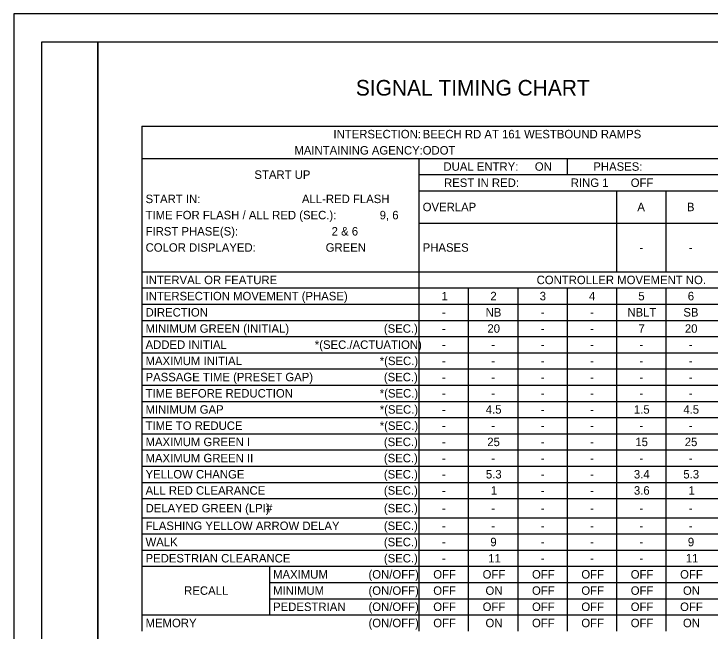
# Model space of a CAD drawing. Extents: x 0 to 34, y 0 to 22.
# Drawn here: x 0 to 12.45, y 10.95 to 22 of the extents above; entities that cross this region are included whole.
import ezdxf

# ---------------------------------------------------------------- set-up
doc = ezdxf.new("R2010")
doc.units = 0
for name, color, linetype in [('SG_P_Text', 7, 'Continuous'), ('SH_Border', 7, 'Continuous'), ('SH_Cut_Line', 7, 'Continuous'), ('SH_Text', 7, 'Continuous')]:
    doc.layers.add(name, color=color, linetype=linetype)

msp = doc.modelspace()

# ---------------------------------------------------------------- linework, layer by layer
at = {"layer": 'SH_Border'}
for points in [[(0.5, 21.5), (1.5, 21.5), (1.5, 0.5), (0.5, 0.5)], [(1.5, 21.5), (33.5, 21.5), (33.5, 0.5), (1.5, 0.5)]]:
    msp.add_lwpolyline(points, close=True, dxfattribs=at)
at = {"layer": 'SH_Cut_Line'}
msp.add_lwpolyline([(0, 0), (34, 0), (34, 22), (0, 22)], close=True, dxfattribs=at)
at = {"layer": 'SH_Text'}
for p, q in [((2.288, 19.994), (7.243, 19.994)), ((2.288, 19.994), (2.288, 19.704)), ((7.243, 19.994), (11.657, 19.994)), ((11.657, 19.994), (14.305, 19.994)), ((2.288, 19.704), (2.288, 19.414)), ((2.288, 19.414), (7.243, 19.414)), ((2.288, 19.414), (2.288, 19.124)), ((7.243, 19.414), (11.657, 19.414)), ((7.243, 19.414), (7.243, 19.124)), ((9.891, 19.414), (9.891, 19.124)), ((11.657, 19.414), (14.305, 19.414)), ((2.288, 19.124), (2.288, 18.834)), ((7.243, 19.124), (11.657, 19.124)), ((7.243, 19.124), (7.243, 18.834)), ((11.657, 19.124), (14.305, 19.124)), ((2.288, 18.834), (2.288, 18.544)), ((7.243, 18.834), (11.657, 18.834)), ((7.243, 18.834), (7.243, 18.544)), ((10.774, 18.834), (10.774, 18.544)), ((11.657, 18.834), (14.305, 18.834)), ((11.657, 18.834), (11.657, 18.544)), ((2.288, 18.544), (2.288, 18.254)), ((7.243, 18.544), (7.243, 18.254)), ((10.774, 18.544), (10.774, 18.254)), ((11.657, 18.544), (11.657, 18.254)), ((2.288, 18.254), (2.288, 17.965)), ((7.243, 18.254), (11.657, 18.254)), ((7.243, 18.254), (7.243, 17.965)), ((10.774, 18.254), (10.774, 17.965)), ((11.657, 18.254), (14.305, 18.254)), ((11.657, 18.254), (11.657, 17.965)), ((2.288, 17.965), (2.288, 17.675)), ((7.243, 17.965), (7.243, 17.675)), ((10.774, 17.965), (10.774, 17.675)), ((11.657, 17.965), (11.657, 17.675)), ((2.288, 17.675), (2.288, 17.385)), ((7.243, 17.675), (7.243, 17.385)), ((10.774, 17.675), (10.774, 17.385)), ((11.657, 17.675), (11.657, 17.385)), ((2.288, 17.385), (7.243, 17.385)), ((2.288, 17.385), (2.288, 17.095)), ((7.243, 17.385), (11.657, 17.385)), ((7.243, 17.385), (7.243, 17.095)), ((11.657, 17.385), (14.305, 17.385)), ((2.288, 17.095), (7.243, 17.095)), ((2.288, 17.095), (2.288, 16.805)), ((7.243, 17.095), (11.657, 17.095)), ((7.243, 17.095), (7.243, 16.805)), ((8.125, 17.095), (8.125, 16.805)), ((9.008, 17.095), (9.008, 16.805)), ((9.891, 17.095), (9.891, 16.805)), ((10.774, 17.095), (10.774, 16.805)), ((11.657, 17.095), (14.305, 17.095)), ((11.657, 17.095), (11.657, 16.805)), ((2.288, 16.805), (7.243, 16.805)), ((2.288, 16.805), (2.288, 16.515)), ((7.243, 16.805), (11.657, 16.805)), ((7.243, 16.805), (7.243, 16.515)), ((8.125, 16.805), (8.125, 16.515)), ((9.008, 16.805), (9.008, 16.515)), ((9.891, 16.805), (9.891, 16.515)), ((10.774, 16.805), (10.774, 16.515)), ((11.657, 16.805), (14.305, 16.805)), ((11.657, 16.805), (11.657, 16.515)), ((2.288, 16.515), (7.243, 16.515)), ((2.288, 16.515), (2.288, 16.225)), ((7.243, 16.515), (11.657, 16.515)), ((7.243, 16.515), (7.243, 16.225)), ((8.125, 16.515), (8.125, 16.225)), ((9.008, 16.515), (9.008, 16.225)), ((9.891, 16.515), (9.891, 16.225)), ((10.774, 16.515), (10.774, 16.225)), ((11.657, 16.515), (14.305, 16.515)), ((11.657, 16.515), (11.657, 16.225)), ((2.288, 16.225), (7.243, 16.225)), ((2.288, 16.225), (2.288, 15.935)), ((7.243, 16.225), (11.657, 16.225)), ((7.243, 16.225), (7.243, 15.935)), ((8.125, 16.225), (8.125, 15.935)), ((9.008, 16.225), (9.008, 15.935)), ((9.891, 16.225), (9.891, 15.935)), ((10.774, 16.225), (10.774, 15.935)), ((11.657, 16.225), (14.305, 16.225)), ((11.657, 16.225), (11.657, 15.935)), ((2.288, 15.935), (7.243, 15.935)), ((2.288, 15.935), (2.288, 15.646)), ((7.243, 15.935), (11.657, 15.935)), ((7.243, 15.935), (7.243, 15.646)), ((8.125, 15.935), (8.125, 15.646)), ((9.008, 15.935), (9.008, 15.646)), ((9.891, 15.935), (9.891, 15.646)), ((10.774, 15.935), (10.774, 15.646)), ((11.657, 15.935), (14.305, 15.935)), ((11.657, 15.935), (11.657, 15.646)), ((2.288, 15.646), (7.243, 15.646)), ((2.288, 15.646), (2.288, 15.356)), ((7.243, 15.646), (11.657, 15.646)), ((7.243, 15.646), (7.243, 15.356)), ((8.125, 15.646), (8.125, 15.356)), ((9.008, 15.646), (9.008, 15.356)), ((9.891, 15.646), (9.891, 15.356)), ((10.774, 15.646), (10.774, 15.356)), ((11.657, 15.646), (14.305, 15.646)), ((11.657, 15.646), (11.657, 15.356)), ((2.288, 15.356), (7.243, 15.356)), ((2.288, 15.356), (2.288, 15.066)), ((7.243, 15.356), (11.657, 15.356)), ((7.243, 15.356), (7.243, 15.066)), ((8.125, 15.356), (8.125, 15.066)), ((9.008, 15.356), (9.008, 15.066)), ((9.891, 15.356), (9.891, 15.066)), ((10.774, 15.356), (10.774, 15.066)), ((11.657, 15.356), (14.305, 15.356)), ((11.657, 15.356), (11.657, 15.066)), ((2.288, 15.066), (7.243, 15.066)), ((2.288, 15.066), (2.288, 14.776)), ((7.243, 15.066), (11.657, 15.066)), ((7.243, 15.066), (7.243, 14.776)), ((8.125, 15.066), (8.125, 14.776)), ((9.008, 15.066), (9.008, 14.776)), ((9.891, 15.066), (9.891, 14.776)), ((10.774, 15.066), (10.774, 14.776)), ((11.657, 15.066), (14.305, 15.066)), ((11.657, 15.066), (11.657, 14.776)), ((2.288, 14.776), (7.243, 14.776)), ((2.288, 14.776), (2.288, 14.486)), ((7.243, 14.776), (11.657, 14.776)), ((7.243, 14.776), (7.243, 14.486)), ((8.125, 14.776), (8.125, 14.486)), ((9.008, 14.776), (9.008, 14.486)), ((9.891, 14.776), (9.891, 14.486)), ((10.774, 14.776), (10.774, 14.486)), ((11.657, 14.776), (14.305, 14.776)), ((11.657, 14.776), (11.657, 14.486)), ((2.288, 14.486), (7.243, 14.486)), ((2.288, 14.486), (2.288, 14.196)), ((7.243, 14.486), (11.657, 14.486)), ((7.243, 14.486), (7.243, 14.196)), ((8.125, 14.486), (8.125, 14.196)), ((9.008, 14.486), (9.008, 14.196)), ((9.891, 14.486), (9.891, 14.196)), ((10.774, 14.486), (10.774, 14.196)), ((11.657, 14.486), (14.305, 14.486)), ((11.657, 14.486), (11.657, 14.196)), ((2.288, 14.196), (7.243, 14.196)), ((2.288, 14.196), (2.288, 13.906)), ((7.243, 14.196), (11.657, 14.196)), ((7.243, 14.196), (7.243, 13.906)), ((8.125, 14.196), (8.125, 13.906)), ((9.008, 14.196), (9.008, 13.906)), ((9.891, 14.196), (9.891, 13.906)), ((10.774, 14.196), (10.774, 13.906)), ((11.657, 14.196), (14.305, 14.196)), ((11.657, 14.196), (11.657, 13.906)), ((2.288, 13.906), (7.243, 13.906)), ((2.288, 13.906), (2.288, 13.616)), ((7.243, 13.906), (11.657, 13.906)), ((7.243, 13.906), (7.243, 13.616)), ((8.125, 13.906), (8.125, 13.616)), ((9.008, 13.906), (9.008, 13.616)), ((9.891, 13.906), (9.891, 13.616)), ((10.774, 13.906), (10.774, 13.616)), ((11.657, 13.906), (14.305, 13.906)), ((11.657, 13.906), (11.657, 13.616)), ((2.288, 13.616), (7.243, 13.616)), ((2.288, 13.616), (2.288, 13.326)), ((7.243, 13.616), (11.657, 13.616)), ((7.243, 13.616), (7.243, 13.326)), ((8.125, 13.616), (8.125, 13.326)), ((9.008, 13.616), (9.008, 13.326)), ((9.891, 13.616), (9.891, 13.326)), ((10.774, 13.616), (10.774, 13.326)), ((11.657, 13.616), (14.305, 13.616)), ((11.657, 13.616), (11.657, 13.326)), ((2.288, 13.326), (7.243, 13.326)), ((2.288, 13.326), (2.288, 12.984)), ((7.243, 13.326), (11.657, 13.326)), ((7.243, 13.326), (7.243, 12.984)), ((8.125, 13.326), (8.125, 12.984)), ((9.008, 13.326), (9.008, 12.984)), ((9.891, 13.326), (9.891, 12.984)), ((10.774, 13.326), (10.774, 12.984)), ((11.657, 13.326), (14.305, 13.326)), ((11.657, 13.326), (11.657, 12.984)), ((2.288, 12.984), (7.243, 12.984)), ((2.288, 12.984), (2.288, 12.694)), ((7.243, 12.984), (11.657, 12.984)), ((7.243, 12.984), (7.243, 12.694)), ((8.125, 12.984), (8.125, 12.694)), ((9.008, 12.984), (9.008, 12.694)), ((9.891, 12.984), (9.891, 12.694)), ((10.774, 12.984), (10.774, 12.694)), ((11.657, 12.984), (14.305, 12.984)), ((11.657, 12.984), (11.657, 12.694)), ((2.288, 12.694), (7.243, 12.694)), ((2.288, 12.694), (2.288, 12.404)), ((7.243, 12.694), (11.657, 12.694)), ((7.243, 12.694), (7.243, 12.404)), ((8.125, 12.694), (8.125, 12.404)), ((9.008, 12.694), (9.008, 12.404)), ((9.891, 12.694), (9.891, 12.404)), ((10.774, 12.694), (10.774, 12.404)), ((11.657, 12.694), (14.305, 12.694)), ((11.657, 12.694), (11.657, 12.404)), ((2.288, 12.404), (7.243, 12.404)), ((2.288, 12.404), (2.288, 12.114)), ((7.243, 12.404), (11.657, 12.404)), ((7.243, 12.404), (7.243, 12.114)), ((8.125, 12.404), (8.125, 12.114)), ((9.008, 12.404), (9.008, 12.114)), ((9.891, 12.404), (9.891, 12.114)), ((10.774, 12.404), (10.774, 12.114)), ((11.657, 12.404), (14.305, 12.404)), ((11.657, 12.404), (11.657, 12.114)), ((2.288, 12.114), (7.243, 12.114)), ((2.288, 12.114), (2.288, 11.824)), ((4.568, 12.114), (4.568, 11.824)), ((7.243, 12.114), (11.657, 12.114)), ((7.243, 12.114), (7.243, 11.824)), ((8.125, 12.114), (8.125, 11.824)), ((9.008, 12.114), (9.008, 11.824)), ((9.891, 12.114), (9.891, 11.824)), ((10.774, 12.114), (10.774, 11.824)), ((11.657, 12.114), (14.305, 12.114)), ((11.657, 12.114), (11.657, 11.824)), ((2.288, 11.824), (2.288, 11.245)), ((4.568, 11.824), (7.243, 11.824)), ((4.568, 11.824), (4.568, 11.245)), ((7.243, 11.824), (11.657, 11.824)), ((7.243, 11.824), (7.243, 11.245)), ((8.125, 11.824), (8.125, 11.245)), ((9.008, 11.824), (9.008, 11.245)), ((9.891, 11.824), (9.891, 11.245)), ((10.774, 11.824), (10.774, 11.245)), ((11.657, 11.824), (14.305, 11.824)), ((11.657, 11.824), (11.657, 11.245)), ((4.568, 11.534), (7.243, 11.534)), ((7.243, 11.534), (11.657, 11.534)), ((11.657, 11.534), (14.305, 11.534)), ((2.288, 11.245), (7.243, 11.245)), ((2.288, 11.245), (2.288, 10.955)), ((7.243, 11.245), (11.657, 11.245)), ((7.243, 11.245), (7.243, 10.955)), ((8.125, 11.245), (8.125, 10.955)), ((9.008, 11.245), (9.008, 10.955)), ((9.891, 11.245), (9.891, 10.955)), ((10.774, 11.245), (10.774, 10.955)), ((11.657, 11.245), (14.305, 11.245)), ((11.657, 11.245), (11.657, 10.955))]:
    msp.add_line(p, q, dxfattribs=at)

# ---------------------------------------------------------------- texts
at = {"layer": 'SG_P_Text'}
msp.add_text('SIGNAL TIMING CHART', height=0.28, dxfattribs=at).set_placement((6.114, 20.538))
at = {"layer": 'SH_Text'}
for s, height, p in [('INTERSECTION:', 0.15153, (5.713, 19.773)), ('BEECH RD AT 161 WESTBOUND RAMPS', 0.15153, (7.309, 19.773)), ('MAINTAINING AGENCY:', 0.15153, (5.015, 19.483)), ('ODOT', 0.1515, (7.309, 19.483)), ('DUAL ENTRY:', 0.15153, (7.68, 19.193)), ('ON', 0.1515, (9.314, 19.193)), ('PHASES:', 0.1515, (10.36, 19.193)), ('START UP', 0.1515, (4.3, 19.048)), ('REST IN RED:', 0.15153, (7.691, 18.903)), ('RING 1', 0.1515, (9.957, 18.903)), ('OFF', 0.1515, (11.029, 18.903)), ('START IN:', 0.1515, (2.354, 18.614)), ('ALL-RED FLASH', 0.15153, (5.15, 18.614)), ('OVERLAP', 0.1515, (7.309, 18.469)), ('A', 0.152, (11.147, 18.469)), ('B', 0.152, (12.034, 18.469)), ('TIME FOR FLASH / ALL RED (SEC.):', 0.15153, (2.354, 18.324)), ('9, 6', 0.1515, (6.54, 18.324)), ('FIRST PHASE(S):', 0.15153, (2.354, 18.034)), ('2 & 6', 0.1515, (5.681, 18.034)), ('COLOR DISPLAYED:', 0.15153, (2.354, 17.744)), ('GREEN', 0.1515, (5.574, 17.744)), ('PHASES', 0.1515, (7.309, 17.744)), ('-', 0.152, (11.184, 17.744)), ('-', 0.152, (12.067, 17.744)), ('INTERVAL OR FEATURE', 0.15153, (2.354, 17.164)), ('CONTROLLER MOVEMENT NO.', 0.15153, (9.346, 17.164)), ('INTERSECTION MOVEMENT (PHASE)', 0.15153, (2.354, 16.874)), ('1', 0.152, (7.647, 16.874)), ('2', 0.152, (8.519, 16.874)), ('3', 0.152, (9.401, 16.874)), ('4', 0.152, (10.282, 16.874)), ('5', 0.152, (11.165, 16.874)), ('6', 0.152, (12.049, 16.874)), ('DIRECTION', 0.1515, (2.354, 16.584)), ('NB', 0.1515, (8.434, 16.584)), ('NBLT', 0.1515, (10.97, 16.584)), ('SB', 0.1515, (11.97, 16.584)), ('-', 0.152, (7.653, 16.584)), ('-', 0.152, (9.419, 16.584)), ('-', 0.152, (10.301, 16.584)), ('MINIMUM GREEN (INITIAL)', 0.15153, (2.354, 16.294)), ('(SEC.)', 0.1515, (6.615, 16.294)), ('20', 0.1515, (8.466, 16.294)), ('7', 0.152, (11.167, 16.294)), ('20', 0.1515, (11.997, 16.294)), ('-', 0.152, (7.653, 16.294)), ('-', 0.152, (9.419, 16.294)), ('-', 0.152, (10.301, 16.294)), ('ADDED INITIAL', 0.15153, (2.354, 16.005)), ('*(SEC./ACTUATION)', 0.15153, (5.38, 16.005)), ('-', 0.152, (7.653, 16.005)), ('-', 0.152, (8.536, 16.005)), ('-', 0.152, (9.419, 16.005)), ('-', 0.152, (10.301, 16.005)), ('-', 0.152, (11.184, 16.005)), ('-', 0.152, (12.067, 16.005)), ('MAXIMUM INITIAL', 0.15153, (2.354, 15.715)), ('*(SEC.)', 0.1515, (6.541, 15.715)), ('-', 0.152, (7.653, 15.715)), ('-', 0.152, (8.536, 15.715)), ('-', 0.152, (9.419, 15.715)), ('-', 0.152, (10.301, 15.715)), ('-', 0.152, (11.184, 15.715)), ('-', 0.152, (12.067, 15.715)), ('PASSAGE TIME (PRESET GAP)', 0.15153, (2.354, 15.425)), ('(SEC.)', 0.1515, (6.615, 15.425)), ('-', 0.152, (7.653, 15.425)), ('-', 0.152, (8.536, 15.425)), ('-', 0.152, (9.419, 15.425)), ('-', 0.152, (10.301, 15.425)), ('-', 0.152, (11.184, 15.425)), ('-', 0.152, (12.067, 15.425)), ('TIME BEFORE REDUCTION', 0.15153, (2.354, 15.135)), ('*(SEC.)', 0.1515, (6.541, 15.135)), ('-', 0.152, (7.653, 15.135)), ('-', 0.152, (8.536, 15.135)), ('-', 0.152, (9.419, 15.135)), ('-', 0.152, (10.301, 15.135)), ('-', 0.152, (11.184, 15.135)), ('-', 0.152, (12.067, 15.135)), ('MINIMUM GAP', 0.15153, (2.354, 14.845)), ('*(SEC.)', 0.1515, (6.541, 14.845)), ('4.5', 0.1515, (8.437, 14.845)), ('1.5', 0.1515, (11.086, 14.845)), ('4.5', 0.1515, (11.969, 14.845)), ('-', 0.152, (7.653, 14.845)), ('-', 0.152, (9.419, 14.845)), ('-', 0.152, (10.301, 14.845)), ('TIME TO REDUCE', 0.15153, (2.354, 14.555)), ('*(SEC.)', 0.1515, (6.541, 14.555)), ('-', 0.152, (7.653, 14.555)), ('-', 0.152, (8.536, 14.555)), ('-', 0.152, (9.419, 14.555)), ('-', 0.152, (10.301, 14.555)), ('-', 0.152, (11.184, 14.555)), ('-', 0.152, (12.067, 14.555)), ('MAXIMUM GREEN I', 0.15153, (2.354, 14.265)), ('(SEC.)', 0.1515, (6.615, 14.265)), ('-', 0.152, (7.653, 14.265)), ('25', 0.1515, (8.464, 14.265)), ('-', 0.152, (9.419, 14.265)), ('-', 0.152, (10.301, 14.265)), ('15', 0.1515, (11.112, 14.265)), ('25', 0.1515, (11.995, 14.265)), ('MAXIMUM GREEN II', 0.15153, (2.354, 13.975)), ('(SEC.)', 0.1515, (6.615, 13.975)), ('-', 0.152, (7.653, 13.975)), ('-', 0.152, (8.536, 13.975)), ('-', 0.152, (9.419, 13.975)), ('-', 0.152, (10.301, 13.975)), ('-', 0.152, (11.184, 13.975)), ('-', 0.152, (12.067, 13.975)), ('YELLOW CHANGE', 0.15153, (2.354, 13.686)), ('(SEC.)', 0.1515, (6.615, 13.686)), ('5.3', 0.1515, (8.439, 13.686)), ('3.4', 0.1515, (11.085, 13.686)), ('5.3', 0.1515, (11.97, 13.686)), ('-', 0.152, (7.653, 13.686)), ('-', 0.152, (9.419, 13.686)), ('-', 0.152, (10.301, 13.686)), ('ALL RED CLEARANCE', 0.15153, (2.354, 13.396)), ('(SEC.)', 0.1515, (6.615, 13.396)), ('-', 0.152, (7.653, 13.396)), ('1', 0.152, (8.529, 13.396)), ('-', 0.152, (9.419, 13.396)), ('-', 0.152, (10.301, 13.396)), ('3.6', 0.1515, (11.086, 13.396)), ('1', 0.152, (12.061, 13.396)), ('DELAYED GREEN (LPI) ', 0.15153, (2.354, 13.079)), ('#', 0.152, (4.507, 13.079)), ('(SEC.)', 0.1515, (6.615, 13.079)), ('-', 0.152, (7.653, 13.079)), ('-', 0.152, (8.536, 13.079)), ('-', 0.152, (9.419, 13.079)), ('-', 0.152, (10.301, 13.079)), ('-', 0.152, (11.184, 13.079)), ('-', 0.152, (12.067, 13.079)), ('FLASHING YELLOW ARROW DELAY', 0.15153, (2.354, 12.763)), ('(SEC.)', 0.1515, (6.615, 12.763)), ('-', 0.152, (7.653, 12.763)), ('-', 0.152, (8.536, 12.763)), ('-', 0.152, (9.419, 12.763)), ('-', 0.152, (10.301, 12.763)), ('-', 0.152, (11.184, 12.763)), ('-', 0.152, (12.067, 12.763)), ('WALK', 0.1515, (2.354, 12.473)), ('(SEC.)', 0.1515, (6.615, 12.473)), ('9', 0.152, (8.518, 12.473)), ('9', 0.152, (12.05, 12.473)), ('-', 0.152, (7.653, 12.473)), ('-', 0.152, (9.419, 12.473)), ('-', 0.152, (10.301, 12.473)), ('-', 0.152, (11.184, 12.473)), ('PEDESTRIAN CLEARANCE', 0.15153, (2.354, 12.183)), ('(SEC.)', 0.1515, (6.615, 12.183)), ('11', 0.1515, (8.482, 12.183)), ('11', 0.1515, (12.013, 12.183)), ('-', 0.152, (7.653, 12.183)), ('-', 0.152, (9.419, 12.183)), ('-', 0.152, (10.301, 12.183)), ('-', 0.152, (11.184, 12.183)), ('MAXIMUM', 0.1515, (4.634, 11.894)), ('(ON/OFF)', 0.1515, (6.34, 11.894)), ('OFF', 0.1515, (7.498, 11.894)), ('OFF', 0.1515, (8.381, 11.894)), ('OFF', 0.1515, (9.264, 11.894)), ('OFF', 0.1515, (10.146, 11.894)), ('OFF', 0.1515, (11.029, 11.894)), ('OFF', 0.1515, (11.912, 11.894)), ('RECALL', 0.1515, (3.044, 11.604)), ('MINIMUM', 0.1515, (4.634, 11.604)), ('(ON/OFF)', 0.1515, (6.34, 11.604)), ('OFF', 0.1515, (7.498, 11.604)), ('ON', 0.1515, (8.432, 11.604)), ('OFF', 0.1515, (9.264, 11.604)), ('OFF', 0.1515, (10.146, 11.604)), ('OFF', 0.1515, (11.029, 11.604)), ('ON', 0.1515, (11.963, 11.604)), ('PEDESTRIAN', 0.1515, (4.634, 11.314)), ('(ON/OFF)', 0.1515, (6.34, 11.314)), ('OFF', 0.1515, (7.498, 11.314)), ('OFF', 0.1515, (8.381, 11.314)), ('OFF', 0.1515, (9.264, 11.314)), ('OFF', 0.1515, (10.146, 11.314)), ('OFF', 0.1515, (11.029, 11.314)), ('OFF', 0.1515, (11.912, 11.314)), ('MEMORY', 0.1515, (2.354, 11.024)), ('(ON/OFF)', 0.1515, (6.34, 11.024)), ('OFF', 0.1515, (7.498, 11.024)), ('ON', 0.1515, (8.432, 11.024)), ('OFF', 0.1515, (9.264, 11.024)), ('OFF', 0.1515, (10.146, 11.024)), ('OFF', 0.1515, (11.029, 11.024)), ('ON', 0.1515, (11.963, 11.024))]:
    msp.add_text(s, height=height, dxfattribs=at).set_placement(p)

doc.saveas('drawing.dxf')
